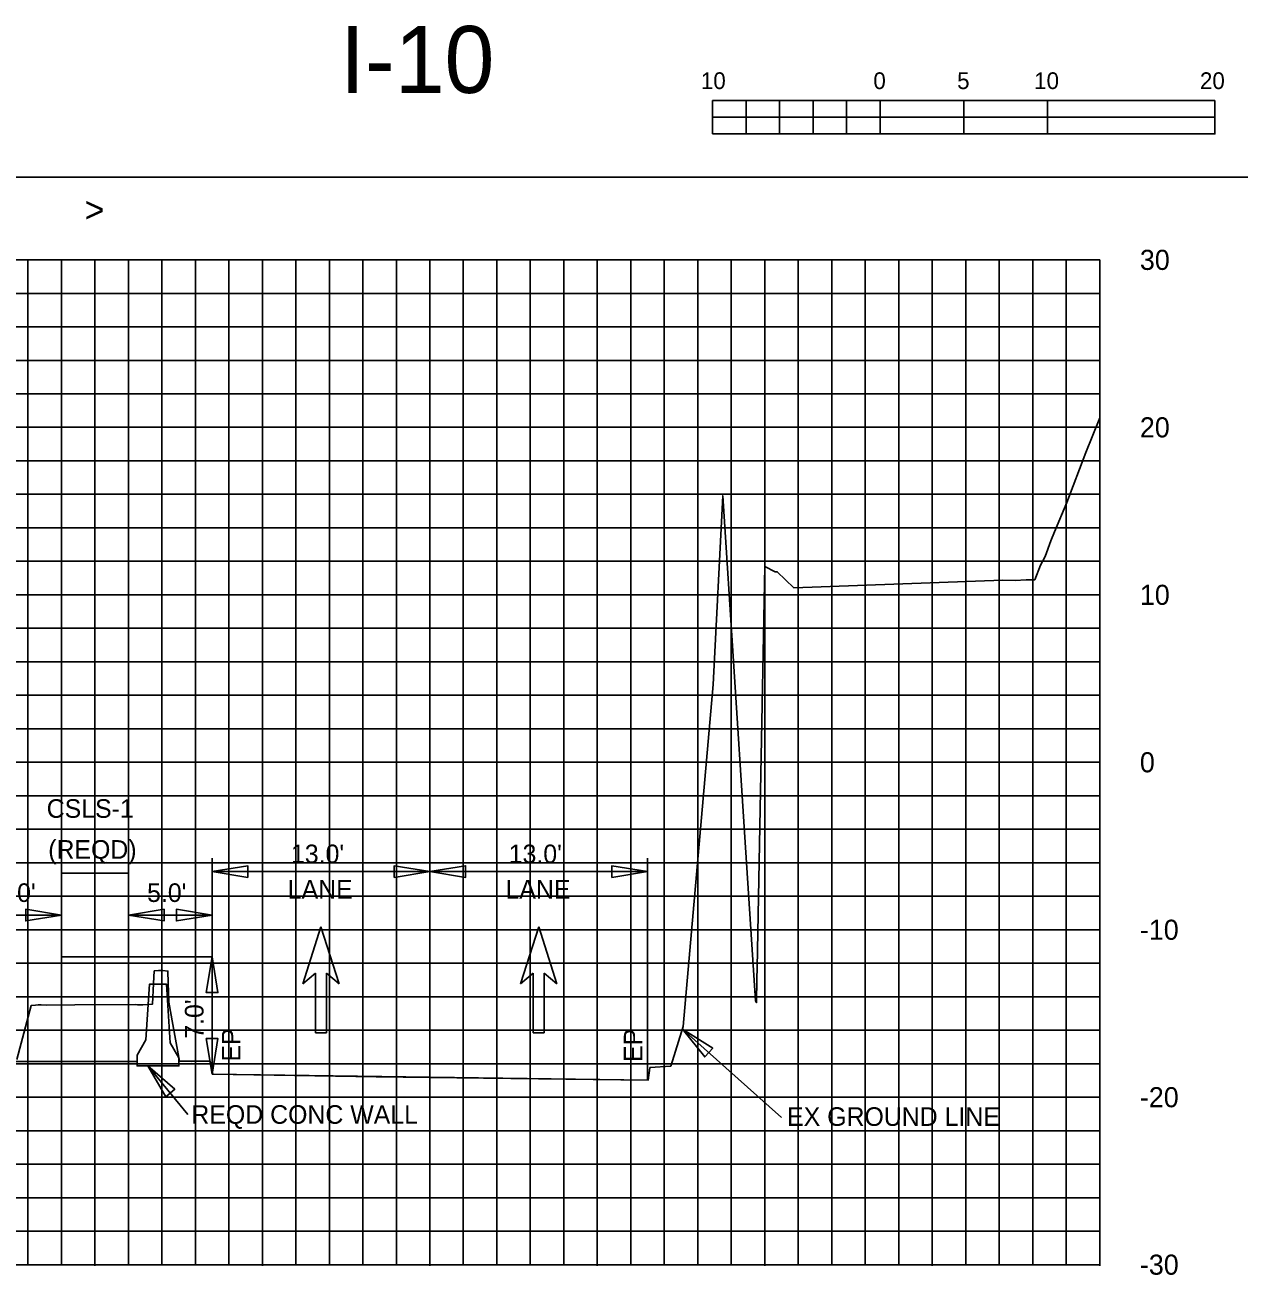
# Model space of a CAD drawing. Extents: x 2193008 to 2198143, y 1236112 to 1237864.
# Drawn here: x 2195384.5 to 2195457, y 1237162.5 to 1237237.1 of the extents above; entities that cross this region are included whole.
import ezdxf

# ---------------------------------------------------------------- set-up
doc = ezdxf.new("R2010")
doc.units = 0
for name, color, linetype in [('3', 7, 'Continuous'), ('31', 7, 'Continuous'), ('60', 7, 'Continuous'), ('CL-CNST', 7, 'Continuous'), ('GSDIMS', 7, 'Continuous'), ('Level 1', 7, 'Continuous'), ('Level 28', 7, 'Continuous'), ('Level 33', 7, 'Continuous'), ('Level 55', 7, 'Continuous'), ('Level 62', 7, 'Continuous'), ('M-ROADS', 7, 'Continuous')]:
    doc.layers.add(name, color=color, linetype=linetype)

msp = doc.modelspace()

# ---------------------------------------------------------------- linework, layer by layer
msp.add_lwpolyline([(2195393.651, 1237175.45), (2195393.134, 1237176.36), (2195392.901, 1237179.862), (2195391.9, 1237179.862), (2195391.678, 1237176.532), (2195391.15, 1237175.622), (2195391.15, 1237174.97), (2195393.651, 1237174.97)], close=True)
at = {"layer": '3'}
for p, q in [((2195228.783, 1237228.046), (2195528.783, 1237228.046)), ((2195395.632, 1237174.481), (2195395.632, 1237187.37)), ((2195408.635, 1237174.305), (2195408.635, 1237187.37)), ((2195421.637, 1237174.13), (2195421.637, 1237187.37)), ((2195388.632, 1237175.229), (2195388.632, 1237181.481)), ((2195429.639, 1237171.891), (2195423.721, 1237177.171)), ((2195394.189, 1237172.08), (2195391.795, 1237174.97))]:
    msp.add_line(p, q, dxfattribs=at)
at = {"layer": '60'}
for p, q in [((2195448.632, 1237163.106), (2195448.632, 1237223.106)), ((2195328.632, 1237163.106), (2195448.632, 1237163.106)), ((2195388.632, 1237163.046), (2195388.632, 1237163.106)), ((2195398.632, 1237163.046), (2195398.632, 1237163.106)), ((2195408.632, 1237163.046), (2195408.632, 1237163.106)), ((2195418.632, 1237163.046), (2195418.632, 1237163.106)), ((2195428.632, 1237163.046), (2195428.632, 1237163.106)), ((2195438.632, 1237163.046), (2195438.632, 1237163.106)), ((2195448.632, 1237163.046), (2195448.632, 1237163.106))]:
    msp.add_line(p, q, dxfattribs=at)
at = {"layer": 'CL-CNST'}
msp.add_line((2195395.513, 1237175.253), (2195395.632, 1237174.481), dxfattribs=at)
for points in [[(2195381.769, 1237175.23), (2195391.15, 1237175.229)], [(2195393.651, 1237175.278), (2195395.513, 1237175.253)], [(2195395.632, 1237174.481), (2195421.673, 1237174.129)]]:
    msp.add_lwpolyline(points, dxfattribs=at)
at = {"layer": 'GSDIMS'}
for p, q in [((2195386.632, 1237186.481), (2195386.632, 1237181.481)), ((2195386.632, 1237186.481), (2195390.632, 1237186.481)), ((2195390.632, 1237186.481), (2195390.632, 1237181.481)), ((2195395.632, 1237186.581), (2195408.635, 1237186.581)), ((2195408.635, 1237186.581), (2195421.637, 1237186.581)), ((2195381.632, 1237183.981), (2195386.632, 1237183.981)), ((2195390.632, 1237183.981), (2195395.632, 1237183.981)), ((2195386.632, 1237181.481), (2195390.632, 1237181.481)), ((2195390.632, 1237181.481), (2195395.632, 1237181.481)), ((2195395.632, 1237181.481), (2195395.632, 1237174.481))]:
    msp.add_line(p, q, dxfattribs=at)
for points in [[(2195395.632, 1237186.581), (2195397.761, 1237186.234), (2195397.761, 1237186.928)], [(2195408.635, 1237186.581), (2195406.506, 1237186.234), (2195406.506, 1237186.928)], [(2195408.635, 1237186.581), (2195410.763, 1237186.234), (2195410.763, 1237186.928)], [(2195421.637, 1237186.581), (2195419.508, 1237186.234), (2195419.508, 1237186.928)], [(2195386.632, 1237183.981), (2195384.504, 1237183.634), (2195384.504, 1237184.329)], [(2195390.632, 1237183.981), (2195392.761, 1237183.634), (2195392.761, 1237184.329)], [(2195395.632, 1237183.981), (2195393.504, 1237183.634), (2195393.504, 1237184.329)], [(2195395.632, 1237181.481), (2195395.285, 1237179.353), (2195395.98, 1237179.353)], [(2195423.721, 1237177.171), (2195425.53, 1237176.027), (2195425.052, 1237175.513)], [(2195395.632, 1237174.481), (2195395.285, 1237176.61), (2195395.98, 1237176.61)], [(2195391.795, 1237174.97), (2195392.872, 1237173.12), (2195393.403, 1237173.579)]]:
    msp.add_lwpolyline(points, close=True, dxfattribs=at)
at = {"layer": 'Level 1'}
for p, q in [((2195455.517, 1237232.63), (2195425.517, 1237232.63)), ((2195425.517, 1237230.63), (2195425.517, 1237232.63)), ((2195427.517, 1237231.63), (2195427.517, 1237232.63)), ((2195431.517, 1237231.63), (2195431.517, 1237232.63)), ((2195435.517, 1237231.63), (2195435.517, 1237232.63)), ((2195435.517, 1237230.63), (2195435.517, 1237232.63)), ((2195440.517, 1237230.63), (2195440.517, 1237232.63)), ((2195445.517, 1237231.63), (2195445.517, 1237232.63)), ((2195445.517, 1237230.63), (2195445.517, 1237232.63)), ((2195455.517, 1237230.63), (2195455.517, 1237232.63)), ((2195427.517, 1237231.63), (2195425.517, 1237231.63)), ((2195429.517, 1237230.63), (2195429.517, 1237231.63)), ((2195431.517, 1237231.63), (2195429.517, 1237231.63)), ((2195433.517, 1237230.63), (2195433.517, 1237231.63)), ((2195435.517, 1237231.63), (2195433.517, 1237231.63)), ((2195440.517, 1237230.63), (2195440.517, 1237231.63)), ((2195445.517, 1237231.63), (2195440.517, 1237231.63)), ((2195455.517, 1237230.63), (2195425.517, 1237230.63)), ((2195429.517, 1237230.63), (2195427.517, 1237230.63)), ((2195433.517, 1237230.63), (2195431.517, 1237230.63)), ((2195440.517, 1237230.63), (2195435.517, 1237230.63)), ((2195455.517, 1237230.63), (2195445.517, 1237230.63))]:
    msp.add_line(p, q, dxfattribs=at)
for points in [[(2195425.517, 1237232.63), (2195427.517, 1237232.63), (2195427.517, 1237231.63), (2195425.517, 1237231.63)], [(2195429.517, 1237232.63), (2195431.517, 1237232.63), (2195431.517, 1237231.63), (2195429.517, 1237231.63)], [(2195433.517, 1237232.63), (2195435.517, 1237232.63), (2195435.517, 1237231.63), (2195433.517, 1237231.63)], [(2195440.517, 1237232.63), (2195445.517, 1237232.63), (2195445.517, 1237231.63), (2195440.517, 1237231.63)], [(2195427.517, 1237231.63), (2195429.517, 1237231.63), (2195429.517, 1237230.63), (2195427.517, 1237230.63)], [(2195431.517, 1237231.63), (2195433.517, 1237231.63), (2195433.517, 1237230.63), (2195431.517, 1237230.63)], [(2195435.517, 1237231.63), (2195440.517, 1237231.63), (2195440.517, 1237230.63), (2195435.517, 1237230.63)], [(2195445.517, 1237231.63), (2195455.517, 1237231.63), (2195455.517, 1237230.63), (2195445.517, 1237230.63)]]:
    msp.add_lwpolyline(points, close=True, dxfattribs=at)
at = {"layer": 'Level 28'}
for p, q in [((2195402.133, 1237183.271), (2195401.044, 1237179.873)), ((2195403.223, 1237179.873), (2195402.133, 1237183.271)), ((2195415.136, 1237183.271), (2195414.046, 1237179.873)), ((2195416.225, 1237179.873), (2195415.136, 1237183.271)), ((2195401.044, 1237179.873), (2195401.807, 1237180.513)), ((2195401.807, 1237180.513), (2195401.807, 1237176.942)), ((2195402.46, 1237176.942), (2195402.46, 1237180.513)), ((2195402.46, 1237180.513), (2195403.223, 1237179.873)), ((2195414.046, 1237179.873), (2195414.809, 1237180.513)), ((2195414.809, 1237180.513), (2195414.809, 1237176.942)), ((2195415.463, 1237176.942), (2195415.463, 1237180.513)), ((2195415.463, 1237180.513), (2195416.225, 1237179.873)), ((2195401.807, 1237176.942), (2195402.46, 1237176.942)), ((2195414.809, 1237176.942), (2195415.463, 1237176.942))]:
    msp.add_line(p, q, dxfattribs=at)
at = {"layer": 'Level 62'}
for p, q in [((2195328.632, 1237223.106), (2195448.632, 1237223.106)), ((2195384.632, 1237163.106), (2195384.632, 1237223.106)), ((2195386.632, 1237163.106), (2195386.632, 1237223.106)), ((2195388.632, 1237163.106), (2195388.632, 1237223.106)), ((2195390.632, 1237163.106), (2195390.632, 1237223.106)), ((2195392.632, 1237163.106), (2195392.632, 1237223.106)), ((2195394.632, 1237163.106), (2195394.632, 1237223.106)), ((2195396.632, 1237163.106), (2195396.632, 1237223.106)), ((2195398.632, 1237163.106), (2195398.632, 1237223.106)), ((2195400.632, 1237163.106), (2195400.632, 1237223.106)), ((2195402.632, 1237163.106), (2195402.632, 1237223.106)), ((2195404.632, 1237163.106), (2195404.632, 1237223.106)), ((2195406.632, 1237163.106), (2195406.632, 1237223.106)), ((2195408.632, 1237163.106), (2195408.632, 1237223.106)), ((2195410.632, 1237163.106), (2195410.632, 1237223.106)), ((2195412.632, 1237163.106), (2195412.632, 1237223.106)), ((2195414.632, 1237163.106), (2195414.632, 1237223.106)), ((2195416.632, 1237163.106), (2195416.632, 1237223.106)), ((2195418.632, 1237163.106), (2195418.632, 1237223.106)), ((2195420.632, 1237163.106), (2195420.632, 1237223.106)), ((2195422.632, 1237163.106), (2195422.632, 1237223.106)), ((2195424.632, 1237163.106), (2195424.632, 1237223.106)), ((2195426.632, 1237163.106), (2195426.632, 1237223.106)), ((2195428.632, 1237163.106), (2195428.632, 1237223.106)), ((2195430.632, 1237163.106), (2195430.632, 1237223.106)), ((2195432.632, 1237163.106), (2195432.632, 1237223.106)), ((2195434.632, 1237163.106), (2195434.632, 1237223.106)), ((2195436.632, 1237163.106), (2195436.632, 1237223.106)), ((2195438.632, 1237163.106), (2195438.632, 1237223.106)), ((2195440.632, 1237163.106), (2195440.632, 1237223.106)), ((2195442.632, 1237163.106), (2195442.632, 1237223.106)), ((2195444.632, 1237163.106), (2195444.632, 1237223.106)), ((2195446.632, 1237163.106), (2195446.632, 1237223.106)), ((2195448.632, 1237163.106), (2195448.632, 1237223.106)), ((2195328.632, 1237221.106), (2195448.632, 1237221.106)), ((2195328.632, 1237219.106), (2195448.632, 1237219.106)), ((2195328.632, 1237217.106), (2195448.632, 1237217.106)), ((2195328.632, 1237215.106), (2195448.632, 1237215.106)), ((2195328.632, 1237213.106), (2195448.632, 1237213.106)), ((2195328.632, 1237211.106), (2195448.632, 1237211.106)), ((2195328.632, 1237209.106), (2195448.632, 1237209.106)), ((2195328.632, 1237207.106), (2195448.632, 1237207.106)), ((2195328.632, 1237205.106), (2195448.632, 1237205.106)), ((2195328.632, 1237203.106), (2195448.632, 1237203.106)), ((2195328.632, 1237201.106), (2195448.632, 1237201.106)), ((2195328.632, 1237199.106), (2195448.632, 1237199.106)), ((2195328.632, 1237197.106), (2195448.632, 1237197.106)), ((2195328.632, 1237195.106), (2195448.632, 1237195.106)), ((2195328.632, 1237193.106), (2195448.632, 1237193.106)), ((2195328.632, 1237191.106), (2195448.632, 1237191.106)), ((2195328.632, 1237189.106), (2195448.632, 1237189.106)), ((2195328.632, 1237187.106), (2195448.632, 1237187.106)), ((2195328.632, 1237185.106), (2195448.632, 1237185.106)), ((2195328.632, 1237183.106), (2195448.632, 1237183.106)), ((2195328.632, 1237181.106), (2195448.632, 1237181.106)), ((2195328.632, 1237179.106), (2195448.632, 1237179.106)), ((2195328.632, 1237177.106), (2195448.632, 1237177.106)), ((2195328.632, 1237175.106), (2195448.632, 1237175.106)), ((2195328.632, 1237173.106), (2195448.632, 1237173.106)), ((2195328.632, 1237171.106), (2195448.632, 1237171.106)), ((2195328.632, 1237169.106), (2195448.632, 1237169.106)), ((2195328.632, 1237167.106), (2195448.632, 1237167.106)), ((2195328.632, 1237165.106), (2195448.632, 1237165.106)), ((2195328.632, 1237163.106), (2195448.632, 1237163.106))]:
    msp.add_line(p, q, dxfattribs=at)
at = {"layer": 'M-ROADS'}
msp.add_lwpolyline([(2195383.973, 1237175.366), (2195384.57, 1237177.609), (2195384.826, 1237178.579), (2195385.088, 1237178.609), (2195385.238, 1237178.626), (2195385.427, 1237178.62), (2195385.764, 1237178.602), (2195387.441, 1237178.622), (2195391.054, 1237178.639), (2195391.167, 1237178.629), (2195391.498, 1237178.628), (2195392.077, 1237178.666), (2195392.127, 1237179.897), (2195392.176, 1237180.649), (2195392.425, 1237180.666), (2195392.555, 1237180.671), (2195392.695, 1237180.664), (2195392.989, 1237180.637), (2195393.013, 1237179.941), (2195393.051, 1237178.771), (2195393.284, 1237177.448), (2195393.685, 1237175.266), (2195394.398, 1237175.243), (2195395.513, 1237175.253), (2195395.566, 1237174.947), (2195395.675, 1237174.481), (2195405.427, 1237174.321), (2195411.832, 1237174.239), (2195421.673, 1237174.129), (2195421.775, 1237174.858), (2195421.779, 1237174.875), (2195423.017, 1237174.962), (2195423.769, 1237177.322), (2195425.552, 1237197.753), (2195426.119, 1237209.021), (2195427.449, 1237188.63), (2195428.083, 1237178.868), (2195428.139, 1237178.761), (2195428.166, 1237180.173), (2195428.178, 1237180.838), (2195428.379, 1237191.378), (2195428.634, 1237204.803), (2195429.26, 1237204.477), (2195429.373, 1237204.484), (2195430.363, 1237203.524), (2195442.846, 1237203.97), (2195443.583, 1237203.959), (2195444.24, 1237204.006), (2195444.73, 1237204.006), (2195444.757, 1237204.006), (2195445.103, 1237204.872), (2195445.374, 1237205.402), (2195445.705, 1237206.322), (2195445.93, 1237206.858), (2195446.673, 1237208.627), (2195447.799, 1237211.609), (2195448.632, 1237213.664)], dxfattribs=at)

# ---------------------------------------------------------------- texts
at = {"layer": '31'}
for s, p in [('30', (2195451.032, 1237222.506)), ('20', (2195451.032, 1237212.506)), ('10', (2195451.032, 1237202.506)), ('0', (2195451.032, 1237192.506)), ('-10', (2195451.032, 1237182.506)), ('-20', (2195451.032, 1237172.506)), ('-30', (2195451.032, 1237162.506))]:
    msp.add_text(s, height=1.2, dxfattribs=at).set_placement(p)
at = {"layer": '60'}
msp.add_text('>', height=1.5, dxfattribs=at).set_placement((2195388.024, 1237225.356))
at = {"layer": 'Level 1'}
for s, height, p in [('10', 0.9991, (2195424.817, 1237233.305)), ('0', 1, (2195435.117, 1237233.304)), ('5', 0.999, (2195440.119, 1237233.304)), ('10', 0.9991, (2195444.717, 1237233.305)), ('20', 0.9991, (2195454.618, 1237233.305))]:
    msp.add_text(s, height=height, rotation=0.0572, dxfattribs=at).set_placement(p)
at = {"layer": 'Level 33'}
msp.add_text('I-10', height=3.9977, rotation=360, dxfattribs=at).set_placement((2195403.274, 1237233.073))
at = {"layer": 'Level 55'}
for s, height, rotation, p in [('CSLS-1', 1.1105, 360, (2195385.752, 1237189.789)), ('(REQD)', 1.1105, 360, (2195385.843, 1237187.346)), ("7.0'", 1.1105, 90, (2195395.118, 1237176.597)), ('EP', 1.1105, 90, (2195397.324, 1237175.236)), ('EP', 1.1105, 90, (2195421.326, 1237175.214)), ('REQD CONC WALL', 1.11046, 360, (2195394.392, 1237171.518))]:
    msp.add_text(s, height=height, rotation=rotation, dxfattribs=at).set_placement(p)
for s, height, p in [("13.0'", 1.1105, (2195400.341, 1237187.081)), ("13.0'", 1.1105, (2195413.343, 1237187.081)), ("5.0'", 1.1105, (2195382.748, 1237184.765)), ("5.0'", 1.1105, (2195391.748, 1237184.765)), ('LANE', 1.1105, (2195400.148, 1237184.971)), ('LANE', 1.1105, (2195413.15, 1237184.971)), ('EX GROUND LINE', 1.11046, (2195429.966, 1237171.394))]:
    msp.add_text(s, height=height, dxfattribs=at).set_placement(p)

doc.saveas('drawing.dxf')
